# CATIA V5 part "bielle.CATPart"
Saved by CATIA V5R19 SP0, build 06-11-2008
Part number: Part2
Bounding box of the stored display mesh (mm): x 0 to 20, y -59.791 to 45, z -45 to 59.791
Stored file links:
  D:\thinkmotion-MPB\Dropbox\CIAO82010_JCF\BOUCHEFRA\580-bouchefra\bielle.CATPart
  C:\Program Files\Dassault Systemes\B20\win_b64\startup\materials\French\Catalog.CATMaterial
  D:\thinkmotion-MPB\Dropbox\CIAO82010_JCF\BOUCHEFRA\580-bouchefra\Part5.CATPart
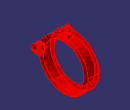
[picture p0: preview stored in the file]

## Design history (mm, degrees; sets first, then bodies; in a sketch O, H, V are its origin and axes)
Sketch1 on yz-plane, origin (0, 0, 0), H (0, 1, 0), V (0, 0, 1)
  circle A1 centre (0, 0) radius 45
  radius A1 = 45
Pad1: profile Sketch1, direction (1, 0, 0), length 20
Set1
  Plane1: linked copy from another document
Body1 (main body)
  Sketch2 on end face of Pad1, origin (20, 0, 0), H (0, 1, 0), V (0, 0, 1)
    point P1 (0, 0)
  Hole1: placed by Sketch2, at (20, 0, 0) direction (-1, 0, 0), diameter 75, through (limit type 3)
  Sketch3 on end face of Pad1, origin (20, 0, 0), H (0, 1, 0), V (0, 0, 1)
    line L1 (-7, 43.7228) -> (-7, 52.7906)
    line L2 (7, 43.7228) -> (7, 52.7906)
    arc A1 centre (0, 52.7906) radius 7 from (7, 52.7906) to (-7, 52.7906) ccw
    point P5 (0, 52.7906)
    line L3 (7, 43.7228) -> (-7, 43.7228)
    radius A1 = 7
    vertical: L1 V, L2 V
    coincidence: P5 V
    tangency: A1 L2, L1 A1
    horizontal: L3 H
  Pad2: profile Sketch3, direction (-1, 0, 0), length 10
  Sketch4 on face of Pad2, origin (20, 0, 0), H (0, 1, 0), V (0, 0, 1)
    point P1 (-0.2598, 51.7769)
  Hole2: placed by Sketch4, at (20, -0.2598, 51.7769) direction (-1, 0, 0), diameter 10, through (limit type 3)
  CircPattern1: of the body so far, instances 2, angular step 90, axis from face of Pad2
